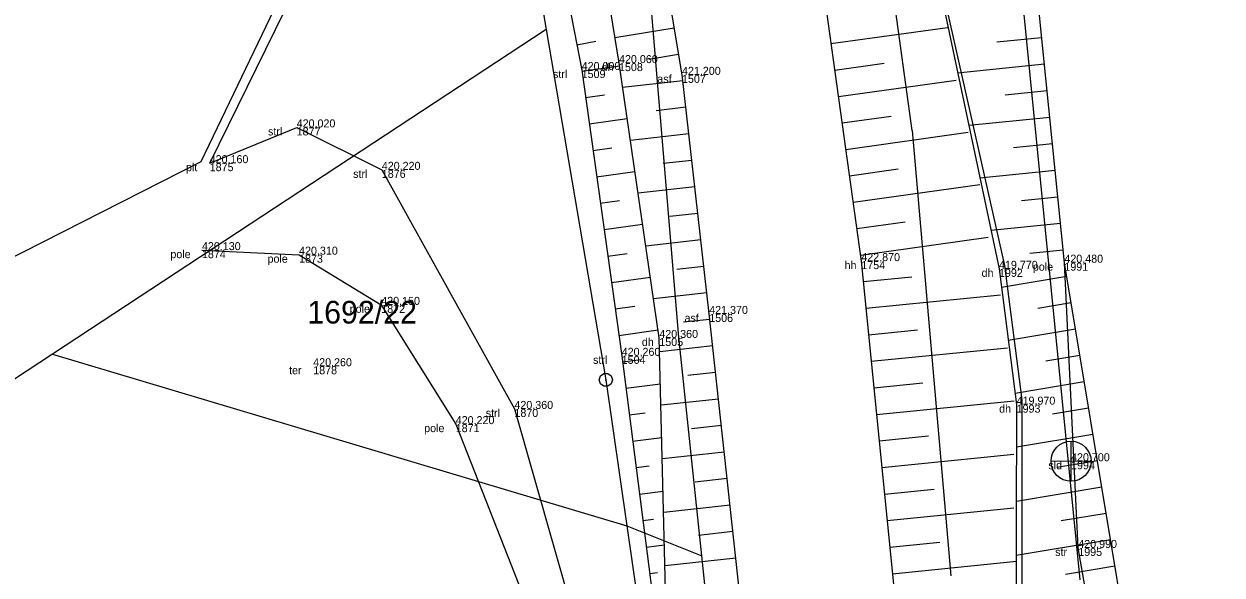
# Model space of a CAD drawing. Extents: x -747792 to -745414, y -1093712 to -1091463.
# Drawn here: x -746681.33 to -746636.43, y -1092595.16 to -1092574.51 of the extents above; entities that cross this region are included whole.
import ezdxf

# ---------------------------------------------------------------- set-up
doc = ezdxf.new("R2010")
doc.units = 0
for name, color, linetype in [('Doplňující texty', 7, 'Continuous'), ('Hladina', 7, 'Continuous'), ('Koleje_dopravní prvky', 7, 'Continuous'), ('Nezařazené objekty', 7, 'Continuous'), ('Nivelační značky_hrany', 7, 'Continuous'), ('Pracovní_bod JDTM STC_VC - výška', 7, 'Continuous'), ('Pracovní_bod PPBP', 7, 'Continuous'), ('Rozhraní ploch', 7, 'Continuous'), ('Stromy_porost', 7, 'Continuous'), ('Výškopis', 7, 'Continuous'), ('Čísla popisná_parcelní', 7, 'Continuous')]:
    doc.layers.add(name, color=color, linetype=linetype)

msp = doc.modelspace()

# ---------------------------------------------------------------- linework, layer by layer
at = {"layer": 'Doplňující texty'}
msp.add_lwpolyline([(-746659.455, -1092587.61), (-746659.33, -1092587.705), (-746659.28, -1092587.85), (-746659.33, -1092587.995), (-746659.455, -1092588.09), (-746659.605, -1092588.09), (-746659.73, -1092587.995), (-746659.78, -1092587.85), (-746659.73, -1092587.705), (-746659.605, -1092587.61)], close=True, dxfattribs=at)
msp.add_lwpolyline([(-746659.555, -1092587.85), (-746659.505, -1092587.85)], dxfattribs=at)
at = {"layer": 'Hladina'}
for p, q in [((-746660.43, -1092576.24), (-746660.43, -1092576.24)), ((-746659.03, -1092575.98), (-746659.03, -1092575.98)), ((-746656.67, -1092576.42), (-746656.67, -1092576.42)), ((-746671.11, -1092578.39), (-746671.11, -1092578.39)), ((-746674.37, -1092579.73), (-746674.37, -1092579.73)), ((-746667.92, -1092579.98), (-746667.92, -1092579.98)), ((-746674.66, -1092582.99), (-746674.66, -1092582.99)), ((-746671.02, -1092583.16), (-746671.02, -1092583.16)), ((-746649.95, -1092583.4), (-746649.95, -1092583.4)), ((-746644.79, -1092583.69), (-746644.79, -1092583.69)), ((-746642.34, -1092583.46), (-746642.34, -1092583.46)), ((-746667.94, -1092585.04), (-746667.94, -1092585.04)), ((-746655.65, -1092585.38), (-746655.65, -1092585.38)), ((-746657.52, -1092586.28), (-746657.52, -1092586.28)), ((-746658.93, -1092586.95), (-746658.93, -1092586.95)), ((-746670.49, -1092587.34), (-746670.49, -1092587.34)), ((-746644.13, -1092588.78), (-746644.13, -1092588.78)), ((-746662.95, -1092588.94), (-746662.95, -1092588.94)), ((-746665.15, -1092589.51), (-746665.15, -1092589.51)), ((-746642.09, -1092590.9), (-746642.09, -1092590.9)), ((-746641.82, -1092594.15), (-746641.82, -1092594.15))]:
    msp.add_line(p, q, dxfattribs=at)
at = {"layer": 'Nezařazené objekty'}
msp.add_lwpolyline([(-746674.37, -1092579.73), (-746664.9, -1092560.44), (-746671.86, -1092546.22), (-746685.68, -1092519.02)], dxfattribs=at)
at = {"layer": 'Nivelační značky_hrany'}
for points in [[(-746676.15, -1092504.12), (-746670.74, -1092515.64), (-746665.13, -1092526.07), (-746661.01, -1092534.91), (-746657.13, -1092545.57), (-746654.31, -1092555.71), (-746652.12, -1092567.85), (-746649.95, -1092583.4), (-746648.25, -1092600.5), (-746646.08, -1092622.58)], [(-746640.293, -1092727.76), (-746642.73, -1092706.84), (-746645.07, -1092684.23), (-746647.45, -1092662.17), (-746649.23, -1092645.87), (-746651.64, -1092623.4), (-746654, -1092600.5), (-746655.65, -1092585.38), (-746656.67, -1092576.42), (-746659.12, -1092561.65), (-746661.88, -1092550.86), (-746667.11, -1092535.97), (-746671.93, -1092526), (-746677.329, -1092516.06)]]:
    msp.add_lwpolyline(points, dxfattribs=at)
at = {"layer": 'Pracovní_bod JDTM STC_VC - výška'}
for points in [[(-746632.74, -1092626.58), (-746635.64, -1092620.77), (-746637.67, -1092615.33), (-746638.38, -1092607.28), (-746642.34, -1092583.46), (-746643.39, -1092573.07), (-746645.13, -1092563.74), (-746647.06, -1092557.12), (-746650.52, -1092546.83), (-746656.13, -1092532.17), (-746659.53, -1092519.12), (-746666.48, -1092509.53), (-746671.18, -1092501.38)], [(-746666.44, -1092549), (-746665.36, -1092551.34), (-746663.2, -1092562.01), (-746660.43, -1092576.24), (-746658.93, -1092586.95), (-746657.16, -1092600.72), (-746656.07, -1092616.52), (-746651.4, -1092662.02)], [(-746647.06, -1092557.12), (-746649.1, -1092557.89), (-746648.35, -1092566.85), (-746644.58, -1092583.56), (-746643.94, -1092588.6), (-746643.94, -1092602.65), (-746640.7, -1092621.81)], [(-746674.37, -1092579.73), (-746671.11, -1092578.39), (-746667.92, -1092579.98), (-746662.95, -1092588.94), (-746660.74, -1092596.69), (-746659.38, -1092604.06), (-746657.87, -1092616.28)], [(-746674.66, -1092582.99), (-746671.02, -1092583.16), (-746667.94, -1092585.04), (-746665.15, -1092589.51), (-746662.1, -1092597.27), (-746660.99, -1092604.7), (-746660.18, -1092611.65), (-746659.07, -1092619.55), (-746657.98, -1092627.96), (-746657.42, -1092636.81), (-746656.61, -1092645.82), (-746656.32, -1092653.69)], [(-746640.7, -1092621.81), (-746638.08, -1092620.93), (-746639.51, -1092607.32), (-746641.82, -1092594.15), (-746642.34, -1092583.46)]]:
    msp.add_lwpolyline(points, dxfattribs=at)
at = {"layer": 'Pracovní_bod PPBP'}
for points in [[(-746674.28, -1092503.22), (-746668.93, -1092514.2), (-746662.98, -1092525.23), (-746658.61, -1092533.49), (-746654.09, -1092544.66), (-746650.92, -1092554.26), (-746648.35, -1092566.85), (-746644.79, -1092583.69), (-746644.13, -1092588.78), (-746644.17, -1092602.45), (-746642.4, -1092621.5)], [(-746643.03, -1092728.31), (-746645.35, -1092706.55), (-746647.64, -1092685.53), (-746650.22, -1092662.21), (-746652.01, -1092645.97), (-746654.41, -1092623.21), (-746657.16, -1092600.72), (-746657.52, -1092586.28), (-746659.03, -1092575.98), (-746661.36, -1092561.58), (-746663.99, -1092551.17), (-746668.72, -1092536.82), (-746673.6, -1092526.76), (-746679.03, -1092516.89)], [(-746656.96, -1092574.669), (-746659.182, -1092575.038)], [(-746651.087, -1092575.25), (-746646.716, -1092574.64)], [(-746660.614, -1092575.297), (-746659.9, -1092575.158)], [(-746643.192, -1092575.031), (-746644.87, -1092575.201)], [(-746656.797, -1092575.656), (-746657.91, -1092575.84)], [(-746660.425, -1092576.279), (-746659.015, -1092576.081)], [(-746650.949, -1092576.241), (-746649.094, -1092575.982)], [(-746643.091, -1092576.026), (-746646.341, -1092576.354)], [(-746656.645, -1092576.644), (-746658.895, -1092576.9)], [(-746650.811, -1092577.231), (-746646.401, -1092576.616)], [(-746642.991, -1092577.021), (-746644.562, -1092577.18)], [(-746660.286, -1092577.269), (-746659.578, -1092577.17)], [(-746656.531, -1092577.637), (-746657.641, -1092577.764)], [(-746650.673, -1092578.222), (-746648.831, -1092577.965)], [(-746642.89, -1092578.016), (-746645.925, -1092578.323)], [(-746660.147, -1092578.26), (-746658.725, -1092578.06)], [(-746656.418, -1092578.631), (-746658.605, -1092578.88)], [(-746650.534, -1092579.212), (-746645.951, -1092578.572)], [(-746660.008, -1092579.25), (-746659.294, -1092579.15)], [(-746642.79, -1092579.011), (-746644.253, -1092579.159)], [(-746656.305, -1092579.625), (-746657.382, -1092579.747)], [(-746659.87, -1092580.24), (-746658.435, -1092580.039)], [(-746650.396, -1092580.202), (-746648.568, -1092579.947)], [(-746642.689, -1092580.006), (-746645.509, -1092580.291)], [(-746656.192, -1092580.618), (-746658.315, -1092580.86)], [(-746650.258, -1092581.193), (-746645.503, -1092580.529)], [(-746659.731, -1092581.231), (-746659.01, -1092581.13)], [(-746642.589, -1092581.001), (-746643.945, -1092581.138)], [(-746656.079, -1092581.612), (-746657.124, -1092581.731)], [(-746659.592, -1092582.221), (-746658.145, -1092582.018)], [(-746650.12, -1092582.183), (-746648.306, -1092581.93)], [(-746642.488, -1092581.996), (-746645.093, -1092582.259)], [(-746649.982, -1092583.174), (-746645.201, -1092582.506)], [(-746655.966, -1092582.605), (-746658.024, -1092582.84)], [(-746659.454, -1092583.211), (-746658.727, -1092583.109)], [(-746642.387, -1092582.991), (-746643.636, -1092583.117)], [(-746655.853, -1092583.599), (-746656.866, -1092583.714)], [(-746659.315, -1092584.202), (-746657.855, -1092583.997)], [(-746649.874, -1092584.168), (-746648.059, -1092583.987)], [(-746642.253, -1092583.981), (-746644.7, -1092584.388)], [(-746655.74, -1092584.593), (-746657.734, -1092584.82)], [(-746649.775, -1092585.163), (-746644.74, -1092584.662)], [(-746659.176, -1092585.192), (-746658.443, -1092585.089)], [(-746642.089, -1092584.967), (-746643.33, -1092585.174)], [(-746655.627, -1092585.586), (-746656.609, -1092585.693)], [(-746659.038, -1092586.182), (-746657.565, -1092585.976)], [(-746649.676, -1092586.158), (-746647.849, -1092585.976)], [(-746641.925, -1092585.954), (-746644.442, -1092586.372)], [(-746655.519, -1092586.58), (-746657.507, -1092586.797)], [(-746649.577, -1092587.153), (-746644.476, -1092586.646)], [(-746641.761, -1092586.94), (-746643.037, -1092587.153)], [(-746658.901, -1092587.173), (-746658.202, -1092587.083)], [(-746655.411, -1092587.574), (-746656.446, -1092587.687)], [(-746658.774, -1092588.165), (-746657.477, -1092587.998)], [(-746649.478, -1092588.148), (-746647.64, -1092587.965)], [(-746641.597, -1092587.927), (-746644.185, -1092588.357)], [(-746655.302, -1092588.568), (-746657.457, -1092588.804)], [(-746649.379, -1092589.143), (-746644.228, -1092588.631)], [(-746658.646, -1092589.157), (-746658.049, -1092589.08)], [(-746641.433, -1092588.913), (-746642.783, -1092589.138)], [(-746655.194, -1092589.563), (-746656.313, -1092589.685)], [(-746658.519, -1092590.148), (-746657.427, -1092590.008)], [(-746649.28, -1092590.138), (-746647.43, -1092589.954)], [(-746641.269, -1092589.9), (-746644.135, -1092590.376)], [(-746655.085, -1092590.557), (-746657.407, -1092590.81)], [(-746649.181, -1092591.133), (-746644.232, -1092590.641)], [(-746641.105, -1092590.886), (-746642.622, -1092591.138)], [(-746658.391, -1092591.14), (-746657.897, -1092591.077)], [(-746654.977, -1092591.551), (-746656.179, -1092591.682)], [(-746649.082, -1092592.128), (-746647.221, -1092591.943)], [(-746640.941, -1092591.873), (-746644.141, -1092592.405)], [(-746658.264, -1092592.132), (-746657.377, -1092592.018)], [(-746654.868, -1092592.545), (-746657.357, -1092592.816)], [(-746648.983, -1092593.123), (-746644.232, -1092592.651)], [(-746640.777, -1092592.859), (-746642.46, -1092593.139)], [(-746658.136, -1092593.124), (-746657.744, -1092593.074)], [(-746654.76, -1092593.539), (-746656.046, -1092593.679)], [(-746658.009, -1092594.116), (-746657.327, -1092594.028)], [(-746648.884, -1092594.118), (-746647.011, -1092593.932)], [(-746640.613, -1092593.846), (-746644.147, -1092594.433)], [(-746654.651, -1092594.533), (-746657.307, -1092594.823)], [(-746648.785, -1092595.114), (-746644.135, -1092594.651)], [(-746657.881, -1092595.108), (-746657.592, -1092595.07)], [(-746640.449, -1092594.832), (-746642.299, -1092595.14)]]:
    msp.add_lwpolyline(points, dxfattribs=at)
at = {"layer": 'Stromy_porost'}
for points in [[(-746664.7, -1092557.45), (-746661.76, -1092574.72)], [(-746674.69, -1092579.67), (-746665.55, -1092560.62)], [(-746648.04, -1092578.51), (-746650.42, -1092561.26)], [(-746656.79, -1092586.25), (-746658.17, -1092569.63)], [(-746644.31, -1092569.61), (-746641.76, -1092595.34)], [(-746661.76, -1092574.72), (-746680.26, -1092586.89)], [(-746661.76, -1092574.72), (-746659.53, -1092587.85)], [(-746648.04, -1092578.51), (-746646.6, -1092595.19)], [(-746790.57, -1092638.58), (-746674.69, -1092579.67)], [(-746655.93, -1092594.45), (-746656.79, -1092586.25)], [(-746680.26, -1092586.89), (-746725.75, -1092616.8)], [(-746680.26, -1092586.89), (-746658.74, -1092593.32)], [(-746659.53, -1092587.85), (-746658.74, -1092593.32)], [(-746658.74, -1092593.32), (-746655.93, -1092594.45)], [(-746658.74, -1092593.32), (-746657.21, -1092603.89)], [(-746655.04, -1092602.92), (-746655.93, -1092594.45)]]:
    msp.add_lwpolyline(points, dxfattribs=at)
at = {"layer": 'Čísla popisná_parcelní'}
for p, q in [((-746642.091, -1092591.648), (-746642.09, -1092590.153)), ((-746641.338, -1092590.906), (-746642.838, -1092590.901))]:
    msp.add_line(p, q, dxfattribs=at)
msp.add_circle((-746642.09, -1092590.9), 0.75, dxfattribs=at)

# ---------------------------------------------------------------- texts
at = {"layer": 'Koleje_dopravní prvky'}
msp.add_text('1692/22', height=0.85, dxfattribs=at).set_placement((-746670.712, -1092585.74))
at = {"layer": 'Rozhraní ploch'}
for s, p in [(' strl', (-746661.616, -1092576.54)), ('1509', (-746660.43, -1092576.54)), (' dh', (-746659.795, -1092576.28)), ('1508', (-746659.03, -1092576.28)), (' asf', (-746657.707, -1092576.72)), ('1507', (-746656.67, -1092576.72)), (' strl', (-746672.296, -1092578.69)), ('1877', (-746671.11, -1092578.69)), (' plt', (-746675.369, -1092580.03)), ('1875', (-746674.37, -1092580.03)), (' strl', (-746669.106, -1092580.28)), ('1876', (-746667.92, -1092580.28)), (' pole', (-746675.954, -1092583.29)), ('1874', (-746674.66, -1092583.29)), (' pole', (-746672.314, -1092583.46)), ('1873', (-746671.02, -1092583.46)), (' hh', (-746650.689, -1092583.7)), ('1754', (-746649.95, -1092583.7)), (' dh', (-746645.555, -1092583.99)), ('1992', (-746644.79, -1092583.99)), (' pole', (-746643.634, -1092583.76)), ('1991', (-746642.34, -1092583.76)), (' pole', (-746669.234, -1092585.34)), ('1872', (-746667.94, -1092585.34)), (' asf', (-746656.687, -1092585.68)), ('1506', (-746655.65, -1092585.68)), (' dh', (-746658.285, -1092586.58)), ('1505', (-746657.52, -1092586.58)), (' strl', (-746660.116, -1092587.25)), ('1504', (-746658.93, -1092587.25)), (' ter', (-746671.506, -1092587.64)), ('1878', (-746670.49, -1092587.64)), (' dh', (-746644.895, -1092589.08)), ('1993', (-746644.13, -1092589.08)), (' strl', (-746664.136, -1092589.24)), ('1870', (-746662.95, -1092589.24)), (' pole', (-746666.444, -1092589.81)), ('1871', (-746665.15, -1092589.81)), (' sld', (-746643.051, -1092591.2)), ('1994', (-746642.09, -1092591.2)), (' str', (-746642.798, -1092594.45)), ('1995', (-746641.82, -1092594.45))]:
    msp.add_text(s, height=0.3, dxfattribs=at).set_placement(p)
at = {"layer": 'Výškopis'}
for s, p in [('420,060', (-746659.03, -1092575.98)), ('420,000', (-746660.43, -1092576.24)), ('421,200', (-746656.67, -1092576.42)), ('420,020', (-746671.11, -1092578.39)), ('420,160', (-746674.37, -1092579.73)), ('420,220', (-746667.92, -1092579.98)), ('420,130', (-746674.66, -1092582.99)), ('420,310', (-746671.02, -1092583.16)), ('422,870', (-746649.95, -1092583.4)), ('419,770', (-746644.79, -1092583.69)), ('420,480', (-746642.34, -1092583.46)), ('420,150', (-746667.94, -1092585.04)), ('421,370', (-746655.65, -1092585.38)), ('420,360', (-746657.52, -1092586.28)), ('420,260', (-746658.93, -1092586.95)), ('420,260', (-746670.49, -1092587.34)), ('420,360', (-746662.95, -1092588.94)), ('419,970', (-746644.13, -1092588.78)), ('420,220', (-746665.15, -1092589.51)), ('420,700', (-746642.09, -1092590.9)), ('420,990', (-746641.82, -1092594.15))]:
    msp.add_text(s, height=0.3, dxfattribs=at).set_placement(p)

doc.saveas('drawing.dxf')
